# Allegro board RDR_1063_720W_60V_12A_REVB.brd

Outline 161.5 x 81.5 mm; copper layers: TOP, DIELECTRIC 1, BOTTOM. Coordinates in mm from the lower left corner of the outline.
Outline path: 0,81.5 99.62,81.5 99.62,75.94 91.82,75.94 91.82,75.05 99.62,75.05 99.62,69.63 108.57,69.63 108.57,81.5 143.5,81.5 143.5,69.05 161.5,69.05 161.5,56.17 143.5,56.17 143.5,45.12 161.5,45.12 161.5,0 63.75,0 63.75,15.68 47.67,15.68 47.67,0 15.24,0 15.24,15.24 0,15.24 0,81.5

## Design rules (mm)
constraint set DEFAULT: min track width 0.254

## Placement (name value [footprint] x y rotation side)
BR1  GBU8K-BP  [PIDAXBRIDGEGBU8]  23.46 19.25 270 bottom
C1  680 pF  [PINPYCAPRAD470X210LS380040#2]  12.9 78.79 180 top
C2  680 pF  [PINPYCAPRAD470X210LS380040]  100.96 36.9 0 top
C3  1 uF  [PINPCAPRAD_12P6X9P2_LS10_D40]  32.16 13.58 270 top
C4  330 nF  [PI_NP_710X355LS590D040]  42.9 55.81 180 top
C5  330 nF  [PI_NP_710X355LS590D040]  33.16 30.72 180 top
C6  1000 pF  [PISMC1206]  97.71 28.53 180 bottom
C7  680 pF  [PINPYCAPRAD470X210LS380040#2]  7.24 58.83 0 top
C8  10 uF  [PISMC0805]  61.34 72.42 180 bottom
C9  100 uF  [PIPOLCAPCLYD16MMD040]  73.75 76.07 270 top
C9A  100 uF  [PIPOLCAPCLYD16MMD040]  59.02 65.76 253.8 top
C9B  100 uF  [PIPOLCAPCLYD16MMD040]  53.94 41.19 325 top
C10  330 pF  [PISMC0603]  120.5 13.54 90 bottom
C11  10 nF  [PI_NP_CAP250X200LS170D030]  71.9 16.7 45 top
C12  0.1 uF  [PISMC0603]  90.92 9.76 90 top
C13  1000 pF  [PISMC0603]  78.9 19.38 90 bottom
C14  1 uF  [PISMC0805]  88.23 19.03 180 bottom
C15  470 pF  [PISMC0603]  84.61 21.4 0 bottom
C16  1 uF  [PISMC0805]  89 7.65 0 top
C17  1 uF  [PISMC0805]  93.02 19.37 180 bottom
C18  470 pF  [PISMC0805]  82.72 20.8 90 bottom
C19  1 uF  [PISMC0805]  71.15 61.4 0 bottom
C20  220 nF  [PISMC0805]  71.15 59.5 0 bottom
C21  100 uF  [PIPOLCAPCLYD320LS140030]  90.18 34.63 308.8 top
C22  10 uF  [PISMC1206]  77.07 64.53 270 bottom
C23  10 uF  [PISMC1206]  79.37 64.53 270 bottom
C24  1 uF  [PISMC0805]  69.29 42.33 180 bottom
C25  0.015 uF  [PINPXCAPRAD18X6MM040]  85.2 79.32 270 top
C26  150 uF  [PIPOLCAPCLYD320LS140030]  120.27 26.83 310 top
C27  100 uF  [PIPOLCAPCYLD250LS100030]  68.36 39.36 180 top
C28  2.2 uF  [PISMC0603]  122.33 5.17 0 bottom
C29  1 uF  [PISMC1206]  72.94 41.22 0 bottom
C30  680 pF  [PINPYCAPRAD470X210LS380040#3]  99.03 41.95 0 top
C31  2.2 uF  [PISMC1206]  116.5 17.6 270 bottom
C32  390 uF  [PIPOLCAPCLYD500LS200040]  154.22 38.52 180 top
C33  330 pF  [PISMC0603]  118.75 16.56 90 bottom
C34  1.5 nF  [PISMC1206]  120.25 65.24 90 bottom
C35  390 uF  [PIPOLCAPCLYD500LS200040]  136.12 38.45 0 top
C36  1 uF  [PISMC1206]  136.44 36.08 0 bottom
C37  1 uF  [PISMC1206]  156.17 33.47 180 bottom
C38  10 uF  [PISMC1206]  116.43 63.01 270 bottom
C39  470 nF  [PISMC0603]  115.57 53.73 90 bottom
C40  150 pF  [PISMC0603]  117.33 69.98 90 bottom
C41  4.7 nF  [PISMC0805]  123.44 72.96 180 bottom
C42  470 nF  [PISMC0805]  113.78 55.84 270 bottom
C43  1 uF  [PISMC0603]  117.01 47.9 90 bottom
C44  470 pF  [PISMC0603]  116.77 76.3 180 bottom
C45  100 nF  [PISMC0805]  97.5 62.5 90 bottom
C46  1 uF  [PISMC0603]  118.65 50.82 90 bottom
C49  10 uF  [PISMC0805]  113 70.4 0 bottom
C50  0.015 uF  [PINPXCAPRAD18X6MM040]  91.37 64.27 90 top
C51  2.2 uF  [PISMC0805]  125.89 27.51 270 bottom
C52  0.47 uF  [PISMC0805]  98.42 11.08 90 bottom
C53  2.2 uF  [PISMC0603]  127.38 51.61 90 bottom
C54  2.2 uF  [PISMC0603]  114.82 46.59 180 bottom
C55  2.2 uF  [PISMC0603]  132.02 5.24 90 bottom
C56  1 uF  [PISMC1206]  131.39 27.04 180 bottom
C57  100 pf  [PISMC0805]  127.53 76.14 270 bottom
C58  2.2 nF  [PISMC0603]  114.8 25.52 0 bottom
C59  2.2 uF  [PISMC0603]  122.33 6.79 0 bottom
C60  2.2 uF  [PISMC0603]  134.07 5.24 90 bottom
C61  100 pF  [PISMC0603]  118.12 66.79 180 bottom
C62  22 nF  [PISMC0805]  156.46 61.88 90 bottom
C63  1 uF  [PISMC1206]  122.38 41.34 180 bottom
C64  10 uF  [PISMC1206]  118.98 62.4 270 bottom
C100  330 pF  [PISMC0603]  80.14 42.58 180 bottom
C102  470 pF  [PISMC0805]  121.03 78.61 270 bottom
C103  10 nF  [PISMC0805]  139.9 29.29 90 bottom
C104  10 uF  [PISMC0805]  133.76 29.08 90 bottom
C105  1 uF  [PISMC1206]  144.98 20.21 0 bottom
C106  680 pF  [PINPYCAPRAD470X210LS380040#2]  147.33 10.35 0 top
C107  680 pF  [PINPYCAPRAD470X210LS380040#2]  157.84 15.35 180 top
C108  330 nF  [PI_NP_710X355LS590D040]  37.09 75.77 180 top
C109  3300 pF  [PI_NP11D5P5MMTD040]  17.57 45.25 180 top
C110  3300 pF  [PI_NP11D5P5MMTD040]  7.6 50.9 0 top
C111  100 pf  [PISMC0805]  133.43 39.7 180 bottom
C112  10 nF  [PISMC0603]  123.27 46.38 180 bottom
C113  470 nF  [PISMC0603]  121.84 48.01 0 bottom
C114  470 nF  [PISMC0603]  118.9 55.52 90 bottom
C115  100 pf  [PISMC0805]  129.74 76.2 270 bottom
D1  1N4148W RHG  [PI_SM_SOD-123_12]  66.12 77.55 90 bottom
D2  1N5408G  [PIDV300X200X060DO15D0201AD]  34.15 22.68 180 top
D3  ES1A-13-F  [PISMDO214AC12]  90.3 39.07 0 bottom
D4  BAV16WS-7-F  [PISMSOD323]  55.94 75.48 270 bottom
D5  ES1J-LTP  [PISMDO214AC12]  80.22 70.48 90 bottom
D6  BAS16HT1G  [PISMSOD323]  69.66 36.8 180 bottom
D7  S1M  [PISMDSMA]  135.98 17.32 90 bottom
D9  BAV16WS-7-F  [PISMSOD323]  111.96 58.15 270 bottom
D10  S1M  [PISMDSMA]  133.63 14 180 bottom
D13  ES1A-13-F  [PISMDO214AC12]  153.43 58.07 180 bottom
D14  ES1A-13-F  [PISMDO214AC12]  159.54 67 180 bottom
D15  ES1J-LTP  [PISMDO214AC12]  97.84 23.08 270 bottom
D16  ES1J-LTP  [PISMDO214AC12]  115.75 22.83 0 bottom
D18  BAS16HT1G  [PISMSOD323]  130.63 25.01 0 bottom
D19  BAS16HT1G  [PISMSOD323]  122.34 1.32 0 bottom
D20  BAV16WS-7-F  [PISMSOD323]  110.23 58.16 270 bottom
D21  BAV16WS-7-F  [PISMSOD323]  122.43 39.27 270 bottom
D22  BAV16WS-7-F  [PISMSOD323]  81.07 40.9 90 top
D23  BAV16WS-7-F  [PISMSOD323]  121.25 33.09 270 bottom
D24  BAV16WS-7-F  [PISMSOD323]  107.87 4.98 270 bottom
E  CON2  [PI_CONN_QC_TAB_2PIN_LS200]  2.62 57.02 180 top
F1  6.3 A  [PI_V_AX_BEL_0697H]  10.9 69.64 90 top
FL1  Hole_156mils  [PI_HOLE_156MIL]  144.04 61.02 0 top
FL2  Hole_156mils  [PI_HOLE_156MIL]  150.11 65.4 0 top
GND1  CON2  [PI_CONN_QC_TAB_2PIN_LS200]  158.32 24.8 180 top
J10  CON10  [PI_HDRF_1X10_SULLINS]  119.81 3.42 0 top
JP1  J  [PI_JUMPER500-16AWG-SLD]  136.37 23.9 270 top
JP2  J  [PI_JUMPER200-16AWG-SLD]  143.08 27.33 270 top
JP3  J  [PI_JUMPER200-16AWG-SLD]  150.8 27.33 270 top
L  CON2  [PI_CONN_QC_TAB_2PIN_LS200]  7.36 67.54 0 top
L1  20 mH  [DER984_INPUT_CMC]  42.11 50.6 270 top
L2  390 uH  [PITOROID2P650X1170LS560060]  14.91 30.1 180 top
L3  PQ26/25  [PIBOBBINPQ262512P]  40.27 27.01 0 top
L5  1 mH  [PI_CMC_1MH]  29.73 65.85 180 top
MTG_HOLE1  M 3  [PIMTGHOLEM3]  3.52 49.78 0 top
MTG_HOLE2  M 3  [PIMTGHOLEM3P15MMUNP]  73 6 0 top
MTG_HOLE3  M 3  [PIMTGHOLEM3P15MMUNP]  97.5 6 0 top
MTG_HOLE4  M 3  [PIMTGHOLEM3P15MMUNP]  11 11.5 0 top
MTG_HOLE5  M 3  [PIMTGHOLEM3]  153.51 4.42 0 top
MTG_HOLE6  M 3  [PIMTGHOLEM3]  153.5 74.5 0 top
MTG_HOLE7  M 3  [PIMTGHOLEM3]  153.5 50.5 0 top
N  CON2  [PI_CONN_QC_TAB_2PIN_LS200]  20.92 56.44 180 top
NOREF  -  []  68.99 31.93 0 top
NOREF#2  -  []  15.24 0 90 top
NOREF#3  -  []  51.44 -90.81 0 top
NOREF#4  -  []  0 81.5 0 top
Q1  NX7002BKR  [PISMSOT23123_1]  60.84 78.2 90 bottom
Q2  DZT2222A-13  [PISMSOT2231234]  77.91 32.67 90 bottom
Q3  DZT2222A-13  [PISMSOT2231234]  129.79 32.86 90 bottom
Q5  DZT2222A-13  [PISMSOT2231234]  112.72 32.83 270 bottom
Q6  IPP111N15N3 G  [PITO220ABVF1]  139.4 77.25 270 bottom
Q7  TN2130K1-G  [PISMSOT23123_1]  139.12 65.27 90 bottom
Q8  DZT2222A-13  [PISMSOT2231234]  82.67 35.3 180 bottom
Q9  IPP111N15N3 G  [PITO220ABVF1]  139.3 53.15 270 bottom
Q10  TN2130K1-G  [PISMSOT23123_1]  138.35 61.68 90 bottom
Q11  MMBTA06LT1  [PISMSOT23123_1]  125.19 10.65 270 bottom
Q12  AONS62922  [PISMPQFN5X6B]  119.58 23.77 270 bottom
Q13  MMBT3906  [PISMSOT23123_1]  83.46 42.01 270 bottom
R1  510 k  [PISMR1206]  38.4 37.95 90 bottom
R2  510 k  [PISMR1206]  32.66 41.26 270 bottom
R3  150 k  [PISMR1206]  97.71 30.81 180 bottom
R4  4.7 k  [PISMR0805]  60.19 75.48 180 bottom
R5  10 k  [PISMR0805]  57.85 77.39 90 bottom
R6  3.6 MegOhm  [PISMR1206]  69.67 19.77 90 bottom
R7  6.2 M  [PISMR1206]  69.67 25.35 0 bottom
R8  6.2 M  [PISMR1206]  66.95 24.39 270 bottom
R9  6.2 M  [PISMR1206]  75.36 27.67 180 bottom
R10  3.74 M  [PISMR1206]  75.73 25.4 0 bottom
R11  2.2  [PISMR0805]  81.42 26.44 0 bottom
R12  332 k  [PISMR0603]  80.85 19.38 90 bottom
R13  13 k  [PISMR0603]  87.67 11.04 270 top
R14  6.2 M  [PISMR1206]  72.67 22.84 0 bottom
R15  162 k  [PISMR0805]  84.69 23.33 0 bottom
R16  162 k  [PISMR0805]  78.33 23.27 0 bottom
R17  1.50 M  [PISMR1206]  88.1 57.4 0 bottom
R18  11.0  [PISMR0805]  71.15 63.3 0 bottom
R19  10.0K  [PISMR0603]  69.17 32.14 270 bottom
R20  1.50 M  [PISMR1206]  92.8 53.54 270 bottom
R21  2.2  [PISMR0805]  77.74 69.9 270 bottom
R22  1 Mohms  [PISMR1206]  88.81 45.57 180 bottom
R23  200  [PISMR1206]  65.75 34.47 0 bottom
R24  11.0  [PISMR0805]  71.53 39.11 270 bottom
R25  150 k  [PISMR1206]  97.71 33.08 180 bottom
R26  100  [PISMR1206]  94.42 26.24 270 bottom
R27  1000  [PISMR0603]  118.94 11.85 0 bottom
R28  100 kOhms  [PISMR2512]  131.93 22.72 270 bottom
R29  316 k  [PISMR0603]  74.46 38.6 0 bottom
R30  100 k  [PISMR0603]  118.75 13.54 90 bottom
R31  340 k  [PISMR0603]  140.13 6.66 270 bottom
R32  300  [PISMR0603]  117.28 9.67 90 bottom
R33  10.0K  [PISMR0603]  144.55 2.04 0 bottom
R34  340 k  [PISMR0603]  118.12 65.17 180 bottom
R35  2.00 M  [PISMR1206]  96.49 1.6 0 bottom
R36  22 k  [PISMR0603]  116.67 68.41 0 bottom
R37  0.01 Ohm  [PISMR2512]  149.6 35.89 270 bottom
R38  0.01 Ohm  [PISMR2512]  145.77 35.89 270 bottom
R39  10 k  [PISMR0805]  136.2 70.67 90 bottom
R40  200  [PISMR0603]  132.7 64.25 0 bottom
R41  2.2  [PISMR0603]  134.31 69.2 180 bottom
R42  470  [PISMR0603]  125.25 5.17 0 bottom
R43  11.5 k  [PISMR0603]  120.5 16.56 90 bottom
R44  511 k  [PISMR0603]  135.99 64.56 90 bottom
R45  11.8 k  [PISMR0603]  130.19 5.17 180 bottom
R46  3 k  [PISMR0805]  133.9 66.05 180 bottom
R47  11.8 k  [PISMR0603]  114.82 44.7 180 bottom
R49  200  [PISMR0603]  129.19 62.44 270 bottom
R50  10 k  [PISMR0805]  136.5 51.05 90 bottom
R51  2.2 M  [PISMR1206]  102.36 3.26 90 bottom
R52  2.2  [PISMR0603]  136.5 56.76 90 bottom
R53  3 k  [PISMR0603]  118.63 49.32 270 bottom
R54  511 k  [PISMR0603]  135.26 60.92 90 bottom
R55  100  [PISMR0603]  106.18 3.97 270 bottom
R57  3 k  [PISMR0805]  133.38 61.99 180 bottom
R58  75 k  [PISMR1206]  119.57 70.85 0 bottom
R59  43 K  [PISMR0805]  113.46 51.8 0 bottom
R60  15 k  [PISMR0603]  113.59 57.63 0 bottom
R61  750 k  [PISMR0603]  110.49 70.66 90 bottom
R62  715 k  [PISMR0603]  110.49 73.83 90 bottom
R63  255 k  [PISMR0603]  112.15 76.28 0 bottom
R64A  5 k  [PIVRES9MMSQUARE]  119.38 37.62 0 top
R65  20 k  [PISMR0603]  84.67 39.42 0 bottom
R66  255 k  [PISMR0603]  122.53 65.44 90 bottom
R68  10.0K  [PISMR0603]  127.3 56.51 180 bottom
R69  100 k  [PISMR0805]  125.57 54.48 270 bottom
R70  43 k  [PISMR0603]  124.97 46.58 90 bottom
R71  1000  [PISMR0603]  129.83 9.83 90 bottom
R72  100 k  [PISMR0603]  128.09 11.26 270 bottom
R74  4.7 k  [PISMR1206]  87.28 34.74 308.1 bottom
R75  1.5 k  [PISMR1206]  126.3 19.16 90 bottom
R76  150 k  [PISMR0603]  127.3 54.85 0 bottom
R76A  1 k  [PISMR0603]  127.38 49.54 270 bottom
R77  22.6 k  [PISMR0603]  86.09 37.78 180 bottom
R79  10.0K  [PISMR0603]  128.85 17.47 90 bottom
R80  340 k  [PISMR0603]  145.97 5.61 180 bottom
R81  10.0K  [PISMR0603]  144.55 3.95 0 bottom
R82  4.7  [PISMR0603]  117.74 25.52 0 bottom
R84  10.0K  [PISMR0603]  106.18 6.91 270 bottom
R85  11.8 k  [PISMR0603]  126.66 6.8 180 bottom
R87  11.8 k  [PISMR0603]  128.75 6.79 0 bottom
R88  10.0K  [PISMR0603]  119.06 1.32 0 bottom
R89  10.0K  [PISMR0603]  85.26 26.57 0 bottom
R90  150  [PISMR1206]  156.62 57.7 0 bottom
R91  2.2 k  [PISMR0805]  111.54 52.78 270 bottom
R94  1.5  [PISMR0805]  132.74 36.35 270 bottom
R95  1.5  [PISMR0805]  114.77 28.28 0 bottom
R96  68 k  [PISMR0603]  123.6 33.2 270 top
R97  100  [PISMR0805]  123.24 62.08 180 bottom
R98  68 k  [PISMR0603]  117.1 38.43 90 bottom
R101  100 k  [PISMR0603]  45.81 44.19 270 bottom
R102  100 k  [PISMR0603]  25.53 44.19 270 bottom
R103  10 k  [PISMR0805]  125.62 76.15 270 bottom
R104  2.00 M  [PISMR0603]  119.29 72.76 90 bottom
R105  1000  [PISMR0603]  136.9 6.66 270 bottom
R106  36 k  [PISMR1206]  153.5 26.38 270 bottom
R107  36 k  [PISMR1206]  140.32 26.78 270 bottom
R108  36 k  [PISMR1206]  156.17 31.17 180 bottom
R109  36 k  [PISMR1206]  156.35 35.78 180 bottom
R110  36 k  [PISMR1206]  136.44 33.77 0 bottom
R111  0  [PISMR0805]  118.86 78.62 270 bottom
R118  100 k  [PISMR0603]  35.59 66.51 270 bottom
R119  100 k  [PISMR0603]  23.84 66.44 270 bottom
R125  10  [PISMR0603]  64.69 73.56 0 bottom
R126  0  [PISMR0603]  116.1 17.37 270 top
R127  0  [PISMR0603]  119.48 19.18 180 top
R128  100 k  [PISMR0603]  130.7 43.38 180 bottom
R130  1.02 k  [PISMR0603]  129.29 41.29 270 bottom
R131  0.0  [PISMR0603]  133.01 41.73 180 bottom
R132  2 k  [PISMR0603]  129.29 44.95 90 bottom
R133  1 k  [PISMR0603]  109.62 54.25 270 bottom
R134  2.2 k  [PISMR0603]  109.62 49.91 90 bottom
R135  43 k  [PISMR0603]  123.27 44.75 180 bottom
R137  2 k  [PISMR0603]  124.25 57.64 90 bottom
R138  100 k  [PISMR0603]  120.95 58.7 90 bottom
R139  5.11 k  [PISMR0603]  143.03 29.98 180 bottom
R140  0.0  [PISMR0603]  136.89 27.51 180 bottom
R141  9.09 k  [PISMR0603]  135.5 29.18 0 top
R145  5 k  [PIVRES9MMSQUARE]  129.72 37.61 0 top
R147  4.7 k  [PISMR0603]  117.24 54.53 90 bottom
R150  0.0  [PISMR0603]  127.18 44.35 90 bottom
R151  15 k  [PISMR0603]  122.58 59.05 270 bottom
R152  11.8 k  [PISMR0603]  116.83 45.82 270 bottom
R153  11.8 k  [PISMR0603]  124.99 43.42 270 bottom
R154  24 k  [PISMR0603]  80.14 40.39 0 bottom
R155  470 k  [PISMR0603]  87.5 42.9 180 bottom
R156  47 k  [PISMR0603]  86.08 41.07 0 bottom
R157  0  [PISMR0805]  130.23 79.43 180 bottom
RL1  SPST NO  [PI_RELAY_OJE]  63.82 71.45 180 top
RL2  SPST NO  [PI_RELAY_SONGCHUAN895_4PIN]  131.63 18.91 90 top
RT1  16  [PIRAD800X250LS330052]  43.92 75.63 270 top
RV1  320 Vac  [PIDISC610X212LS295X95040]  17.67 75.41 270 top
SG1  0.25mm gap  [PI_SPARK_GAP_0P25MM]  33.22 65.83 270 bottom
SG2  0.25mm gap  [PI_SPARK_GAP_0P25MM]  26.22 65.71 270 bottom
SG3  0.25mm gap  [PI_SPARK_GAP_0P25MM]  42.45 43.46 270 bottom
SG4  0.25mm gap  [PI_SPARK_GAP_0P25MM]  29.08 43.31 270 bottom
T1  PQ35/35  [PI_BOBBIN_BPQ35_35_12P]  115.13 62.93 0 top
T2  EE16  [PI_BOBBIN_EE16_10P_YW-527-00B]  106.8 25.8 0 top
U1  CAP300DG  [PI_IC_SMD_SO8_CAPZERO]  38.2 46.74 270 bottom
U2  PFS7539L  [PIICLBENDESIPLG]  92.49 13.96 0 bottom
U3  LCS7268Z  [PI_POWEDIP_B18PAUNP]  74.37 51.31 180 bottom
U4  TL431CDBZR  [PISMSOT23123_1]  119.23 45.07 0 bottom
U5  LM358D  [PISMSO8]  122.18 52.8 0 bottom
U6  LSR2000C-H005  [PI_IC_INSOP_24D]  113 68.6 180 bottom
U7  INA180A1IDBVR  [PISMSOT235]  137.92 31.22 270 bottom
U8  TLV76050DBZR  [PISMSOT23132]  124.23 25.93 270 bottom
U9  TCLT1000  [PISM-4DIP-SLM-1]  103.82 46.76 180 bottom
U10  INN3692C-H606  [PI_IC_INSOP_24D]  113.4 17.63 180 bottom
UNK+60V1  CON2  [PI_CONN_QC_TAB_2PIN_LS200]  139.7 13.45 0 top
VR1  MMSZ5250B-7-F  [PI_SM_SOD-123_12]  104.43 4.8 90 bottom
VR2  MMSZ5250B-7-F  [PI_SM_SOD-123_12]  65 31.1 180 bottom
VR5  MMSZ5267BT1G  [PI_SM_SOD-123_12]  128.86 22.78 270 bottom
VR7  MMSZ5243BT1G  [PI_SM_SOD-123_12]  113.94 40.1 180 bottom
VR8  MMSZ5241B-7-F  [PI_SM_SOD-123_12]  126.72 29.95 270 top
VR10  MMSZ5242C-E3-08  [PI_SM_SOD-123_12]  88.95 29.11 0 bottom
VR11  MMSZ5267BT1G  [PI_SM_SOD-123_12]  158.35 62.11 90 bottom

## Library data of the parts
BR1 = DISCRETE BRIDGE_+~~-: alternate symbols: (pidaxbridgegbu8_horz)
C1 C2 C4 C5 C7 C11 C29-C31 C34 C36 C37 C56 C63 C105-C110 = CAP NP
C3 = CAP NP: alternate symbols: (pinpcaprad_12p6x9p2_ls10_d400H)
C6 C22 C23 C38 C64 = CAP NP: alternate symbols: (pismc1206_1)
C8 C49 = CAP NP: alternate symbols: (Unisem_RMCF0805UL,CC0805,pismc0805_1)
C9 C9A C9B = CAP POL: alternate symbols: (pipolcapclyd16x37mmD040H)
C10 C33 C40 C43 C46 = CAP NP: alternate symbols: (Unisem_RMCF0603UL,pismc0603_1)
C12 C13 C15 C28 C39 C44 C53-C55 C58-C61 C100 C112-C114 = CAP NP: alternate symbols: (Unisem_RMCF0603UL)
C14 C16-C20 C24 C41 C42 C45 C51 C52 C57 C62 C102-C104 C111 C115 = CAP NP: alternate symbols: (Unisem_RMCF0805UL)
C21 C26 = CAP POL: alternate symbols: (pipolcapclyd320ls140030430h)
C25 C50 = CAP NP: alternate symbols: (pinpxcaprad18x6x12p1mm040H)
C27 = CAP POL: alternate symbols: (pipolcapcyld250ls100030h)
C32 C35 = CAP POL
D1 = DIODE: alternate symbols: (pi_sm_sod-123_12_1)
D2 = DIODE: alternate symbols: (pidv300x472x060do14wbead,pidax800x225060do15do201ad,pidv300x200x060do14wbead)
D3 D5 D7 D10 D13-D16 = DIODE
D4 D6 D9 D18-D24 = DIODE: alternate symbols: (SOD323_UL_IPC,pismsod323_1)
E = CON1_2P_TAB_1
F1 = FUSE: alternate symbols: (PI_V_AX_BEL_0697H_H)
FL1 FL2 = FlyingLead
GND1 UNK+60V1 = CON1_2P_TAB
J10 = HEADER10x1F
JP1-JP3 = JUMPER_1
L = CON1_2P_TAB_0
L1 L5 = TORRID 4P_14_23
L2 = INDUCTOR
L3 = BPQ26/25_12P/GENERIC
MTG_HOLE1-MTG_HOLE7 = MTG_HOLE_M3
N = CON1_2P_TAB_2
Q1 Q7 Q10 = FET_N_GSD
Q2 Q3 Q5 Q8 = NPN_BCEC
Q6 Q9 = FET_N_GDS: alternate symbols: (PI_TO220AB,PITO220ABVF1R,pidvto2203vf1h)
Q11 = NPN_BEC
Q12 = FET_N_SGD_123_4_5678
Q13 = PNP_BEC
R1-R3 R6-R10 R14 R17 R20 R22 R23 R25 R26 R28 R35 R37 R38 R51 R58 R74 R75 R106-R110 = R
R4 R5 R11 R15 R16 R18 R21 R24 R39 R46 R50 R57 R59 R69 R91 R94 R95 R97 R103 R111 R157 = R: alternate symbols: (Unisem_RMCF0805UL)
R12 R13 R19 R27 R29-R34 R36 R40-R45 R47 R49 R52-R55 R60-R63 R65 R66 R68 R70-R72 R76 R76A R77 R79-R82 R84 R85 R87-R89 R96 R98 R101 R102 R104 R105 R118 R119 R125-R128 R130 R131 R133-R135 R138-R141 R147 R150-R156 = R: alternate symbols: (Unisem_RMCF0603UL)
R64A R145 = POT
R90 = R: alternate symbols: (pismr1206_1)
R132 R137 = R: alternate symbols: (Unisem_RMCF0603UL,pismr0603_1)
RL1 = RELAY SPST_NO_OMRON-G6RL
RL2 = RELAY SPST_NO_895-1A
RT1 = THERMISTOR
RV1 = VARISTOR
SG1-SG4 = SPARK_GAP
T1 = BPQ35/35_12P/GENERIC
T2 = BEI16_10P/GENERIC
U1 = CAPZero
U2 = HIPERPFS-3-eSIP-16C: alternate symbols: (piiclbendesiplg_socket)
U3 = HiperLCS2-HB: alternate symbols: (pi_PoweDIP_B18pNH)
U4 = TL431CDBZR
U5 = LM358
U6 = HiperLCS2-SR
U7 = INA180A1IDBVR
U8 = TLV76050DBZR
U9 = OPTO_DIP
U10 = Inno3EP_P15
VR1 VR2 VR5 VR7 VR8 VR10 VR11 = DIODE_ZENER

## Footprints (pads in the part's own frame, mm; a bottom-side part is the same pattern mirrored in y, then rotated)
DER984_INPUT_CMC
  round 3.048 hole 1.524: 1(1.854,0.635) 2(1.676,-13.36) 3(13.183,-13.36) 4(13.386,0.635)
PI_BOBBIN_BPQ35_35_12P
  rect 3.048x3.048 hole 1.778: 1(-17.75,15)
  round 3.048 hole 1.778: 2(-17.75,9.92) 3(-44.598,-83.679) 4(-48.001,-83.654) 5(-17.75,-10.4) 6(-40.229,-82.714) 7(17.81,-15.48) 8(17.81,-10.4) 9(17.81,-5.32) 10(-36.444,-83.654) 11(17.81,9.92) 12(17.81,15)
PI_BOBBIN_EE16_10P_YW-527-00B
  rect 2.032x2.032 hole 1.168: 1(-5.25,6.5)
  round 2.032 hole 1.168: 2(-5.25,3.25) 3(-5.25,0) 4(-23.817,-46.811) 5(-5.25,-6.5) 6(-21.471,-44.041) 7(5.25,-3.25) 8(-24.011,-44.171) 9(5.25,3.25) 10(-21.014,-46.459)
PI_CMC_1MH
  round 2.54 hole 1.27: 1(-3.5,-4.5) 2(3.5,-4.5) 3(3.5,4.5) 4(-3.5,4.5)
PI_CONN_QC_TAB_2PIN_LS200
  rect 3.048x3.048 hole 1.524: 1(0,-2.489)
  round 3.048 hole 1.524: 2(0,2.512)
PI_HDRF_1X10_SULLINS
  rect 1.6x1.6 hole 0.9: 1(0,0)
  round 1.6 hole 0.9: 2(2.54,0) 3(5.08,0) 4(7.62,0) 5(10.16,0) 6(12.7,0) 7(15.24,0) 8(17.78,0) 9(20.32,0) 10(22.86,0)
PI_HOLE_156MIL
  round 6.35 hole 3.962: 1(0,0)
PI_IC_INSOP_24D
  rect 1.75x0.45 smd: 1(0,0) 2(0,-0.75) 3(0,-1.5) 4(0,-2.25) 5(0,-3) 6(0,-3.75) 7(0,-4.5) 8(0,-5.25) 9(0,-6) 10(0,-6.75) 11(0,-7.5) 12(0,-8.25) 13(12.89,-8.25) 14(12.89,-7.5) 15(12.89,-6.75) 24(12.89,0)
  custom 0.438x0.438 smd: 16(12.89,-4.67)
PI_IC_SMD_SO8_CAPZERO
  rect 0.599x2.2 smd: 1(0,0) 2(1.27,0) 3(2.54,0) 4(3.81,0) 5(3.81,5.199) 6(2.54,5.199) 7(1.27,5.199) 8(0,5.199)
PI_JUMPER200-16AWG-SLD
  round 3.048 hole 1.778: 1(0,0) 2(5.08,0)
PI_JUMPER500-16AWG-SLD
  round 3.048 hole 1.778: 1(0,0) 2(12.7,0)
PI_NP11D5P5MMTD040
  round 2.032 hole 1.016: 1(0,0) 2(10,0)
PI_NP_710X355LS590D040
  round 2.032 hole 1.016: 1(0,0) 2(15,0)
PI_NP_CAP250X200LS170D030
  round 1.524 hole 0.762: 1(-2.159,0) 2(2.159,0)
PI_POWEDIP_B18PAUNP
  round 3.15 hole 3.15 unplated: (-13.07,0.08) (11.93,0.08)
  rect 1.473x1.473 hole 0.864: 1(-8.55,-5.97)
  round 1.473 hole 0.864: 2(-6.65,-5.97) 3(-4.75,-5.97) 4(-2.85,-5.97) 5(-0.95,-5.97) 6(0.95,-5.97) 7(2.85,-5.97) 8(4.75,-5.97) 9(6.65,-5.97) 10(8.55,-5.97) 11(8.55,5.97) 13(4.75,5.97) 14(2.85,5.97) 15(0.95,5.97) 16(-0.95,5.97) 17(-2.85,5.97) 18(-4.75,5.97) 20(-8.55,5.97)
PI_RELAY_OJE
  rect 2.032x2.032 hole 1.524: 1(0,0)
  round 2.032 hole 1.575: 2(0,-7.6) 3(15.24,0) 4(12.7,-7.6)
PI_RELAY_SONGCHUAN895_4PIN
  rect 1.321x1.321 hole 0.787: 1(-5.1,-5)
  round 1.397 hole 0.864: 2(-39.35,43.514) 3(-5.1,5) 4(-7.6,0)
PI_SM_SOD-123_12
  rect 1.143x1.397 smd: 1(-1.498,0) 2(2.007,0)
PI_SPARK_GAP_0P25MM
  custom 0.5x0.5 smd: 1(-1.125,0) 2(1.125,0)
PI_V_AX_BEL_0697H
  round 1.524 hole 0.762: 1(0,0) 2(5.08,0)
PIBOBBINPQ262512P
  rect 2.032x2.032 hole 1.27: 1(32.918,-43.51)
  round 2.032 hole 1.27: 2(0,-3.81) 3(40.462,-43.155) 4(0,-15.24) 5(24.054,-43.028) 6(27.737,-43.002) 7(26.111,-44.958) 8(25.4,-19.05) 9(38.075,-43.332) 10(35.585,-43.358) 11(30.175,-43.764) 12(23.622,-45.72)
PIDAXBRIDGEGBU8
  rect 3.048x3.048 hole 1.778: 1(0,0)
  round 3.048 hole 1.778: 2(5.08,0) 3(10.16,0) 4(15.24,0)
PIDISC610X212LS295X95040
  round 2.032 hole 1.016: 1(-2.1,-0.5) 2(8.993,-1.413)
PIDV300X200X060DO15D0201AD
  rect 3.048x3.048 hole 1.524: 1(0,0)
  round 3.048 hole 1.524: 2(7.62,0)
PIICLBENDESIPLG
  rect 1.27x1.27 hole 0.787: 1(0,0)
  round 1.27 hole 0.787: 3(-1.93,-2.388) 4(-2.896,0) 5(-3.861,-2.388) 6(-4.826,0) 7(-5.791,-2.388) 8(-6.756,0) 9(-7.722,-2.388) 10(-8.687,0) 11(-9.652,-2.388) 13(-11.582,0) 14(-12.548,-2.388) 16(-14.478,0)
PIMTGHOLEM3
  round 6.35 hole 3.912: 1(0,0)
PIMTGHOLEM3P15MMUNP
  round 3.15 hole 3.15 unplated: (0,0)
PINPCAPRAD_12P6X9P2_LS10_D40
  round 2.032 hole 1.016: 1(0,0) 2(10,0)
PINPXCAPRAD18X6MM040
  round 2.032 hole 1.016: 1(0,0) 2(15,0)
PINPYCAPRAD470X210LS380040
  round 3.2 hole 1.6: 1(-1.674,1.373) 2(10.363,0.381)
PINPYCAPRAD470X210LS380040#2
  round 3.2 hole 1.6: 1(0,0) 2(9.652,0)
PINPYCAPRAD470X210LS380040#3
  round 3.2 hole 1.6: 1(-2.076,1.321) 2(10.585,0.737)
PIPOLCAPCLYD16MMD040
  rect 2.032x2.032 hole 1.016: 1(0,0)
  round 2.032 hole 1.016: 2(7.62,0)
PIPOLCAPCLYD320LS140030
  rect 1.524x1.524 hole 0.762: 1(-1.778,0)
  round 1.524 hole 0.762: 2(1.778,0)
PIPOLCAPCLYD500LS200040
  rect 2.032x2.032 hole 1.016: 1(0,0)
  round 2.032 hole 1.016: 2(5,0)
PIPOLCAPCYLD250LS100030
  rect 1.524x1.524 hole 0.762: 1(-1.27,0)
  round 1.524 hole 0.762: 2(1.27,0)
PIRAD800X250LS330052
  round 2.54 hole 1.321: 1(0,0) 2(8.382,0)
PISM-4DIP-SLM-1
  rect 1.6x1 smd: 1(-4.85,1.27) 2(-4.85,-1.27) 3(4.85,-1.27) 4(4.85,1.27)
PISMC0603
  rect 0.813x0.965 smd: 1(0,0) 2(1.422,0)
PISMC0805
  rect 1.27x1.27 smd: 1(0,0) 2(2.134,0)
PISMC1206
  rect 1.524x1.524 smd: 1(0,0) 2(3.302,0)
PISMDO214AC12
  rect 2.54x2.286 smd: 1(0,0) 2(4.318,0)
PISMDSMA
  rect 2.032x2.032 smd: 1(0,0) 2(4.013,0)
PISMPQFN5X6B
  rect 0.406x1.27 smd: 1(0,0) 2(1.27,0) 3(2.54,0) 4(3.81,0)
  rect 0.406x1.219 smd: 5(3.81,5.588) 6(2.54,5.588) 7(1.27,5.588) 8(0,5.588)
PISMR0603
  rect 0.813x0.965 smd: 1(0,0) 2(1.422,0)
PISMR0805
  rect 1.27x1.27 smd: 1(0,0) 2(2.134,0)
PISMR1206
  rect 1.524x1.524 smd: 1(0,0) 2(3.302,0)
PISMR2512
  rect 1.93x3.048 smd: 1(0,0) 2(5.994,0)
PISMSO8
  rect 0.61x1.448 smd: 1(-1.905,-2.73) 2(-0.635,-2.73) 3(0.635,-2.73) 4(1.905,-2.73) 5(1.905,2.731) 6(0.635,2.731) 7(-0.635,2.731) 8(-1.905,2.731)
PISMSOD323
  rect 0.762x1.27 smd: 1(0,0) 2(2.54,0)
PISMSOT235
  rect 0.686x1.016 smd: 1(0,0) 2(1.016,0) 3(2.032,0) 4(2.032,2.413) 5(0,2.413)
PISMSOT23123_1
  rect 0.864x1.016 smd: 1(-0.93,-1.1) 2(0.95,-1.1)
  rect 0.864x1.27 smd: 3(0.01,1.186)
PISMSOT23132
  rect 0.864x1.016 smd: 1(-1.88,0) 2(0,0)
  rect 0.864x1.27 smd: 3(-0.94,2.286)
PISMSOT2231234
  rect 1.219x2.235 smd: 1(-2.286,-6.198) 2(0,-6.198) 3(2.286,-6.198)
  rect 3.607x2.235 smd: 4(0,0)
PITO220ABVF1
  round 1.524 hole 1.016: 1(-0.025,0) 2(2.515,0) 3(5.055,0)
PITOROID2P650X1170LS560060
  round 3.048 hole 1.524: 1(0.914,0.051) 2(13.106,-0.025)
PIVRES9MMSQUARE
  round 2.032 hole 1.041: 1(-5.08,0)
  rect 1.524x1.524 hole 0.762: 2(-2.54,5.08) 3(0,0)

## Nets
5VL: C29.1 C45.1 D22.1(K) Q13.2(EMITTER) R65.2 R156.1 U3.7 U6.15
5VS: C49.1 U6.1
+2.5V: C43.1 R53.2 R152.1 R153.1 U4.1 U4.2(VREF)
+5V: C51.1 C104.2 U7.5 U8.1
+12V: C26.1 C46.1 D10.1(K) J10.2 R27.1 R30.1 R53.1 R75.1 R95.2 RL2.1 T2.9 U5.8 U8.2 U10.6
+12V_PMY: C8.1 C17.1 Q8.3 R125.1 RL1.1 U2.1(VCC)
GND_EARTH: C1.2 C7.1 C109.2 C110.1 E.1 E.2 MTG_HOLE1.1
AUX_PRI: C21.1 D3.1(K) D24.2 Q2.2 Q2.4 R11.1 R19.1 R74.1
BAT+: JP1.2 R28.2 R31.1 RL2.4 UNK+60V1.1 UNK+60V1.2
BAT-: C105.2 GND1.1 GND1.2 JP3.2 R106.2
BAT-ADC: J10.9 R31.2 R33.1
BM: D4.1(K) R4.2
BP_RELAY: Q2.3 R23.2
BPP: C27.1 D5.2 D6.1(K) R24.2
BPS: C38.1 C63.1 D21.1(K) D23.1(K) R40.1 R49.1 R97.1 U6.7
CS+: C107.2 JP3.1 R37.2 R38.2 R106.1 R139.1
D5: D14.2 FL2.1 Q6.2 Q7.3
FB: C61.2 D9.1(K) D20.1(K) R34.2 R36.1 U6.5
FL: U3.6 U6.14
GD: C24.2 C27.2 U3.10
GP: C29.2 C45.2 C100.2 R29.2 U3.4 U6.16 U9.3(E)
GSA: C2.2 C26.2 C28.1 C30.2 C31.1 C32.2 C33.2 C35.2 C36.2 C37.2 C38.2 C43.2 C46.2 C51.2 C53.2 C54.2 C55.1 C56.2 C59.1 C60.1 C63.2 C64.2 C103.2 C104.1 C111.2 C114.2 D16.2 J10.1 J10.7 Q6.3(S) Q9.3(S) Q11.2(EMITTER) Q12.1 Q12.2 Q12.3(S3) R33.2 R37.1 R38.1 R39.1 R43.2 R50.1 R64A.3 R69.1 R72.2 R75.2 R76.1 R81.2 R82.2 R108.2 R109.2 R110.2 R126.1 R130.2 R134.1 R138.1 R140.1 R145.3 U4.3 U5.4 U6.12 U7.2 U8.3 U9.2 U10.1 U10.2 VR7.2 VR8.2
GSB: C34.2 C40.2 C41.2 C49.2 C57.2 C61.1 C115.2 R36.2 R66.2 R103.2 R104.2 T1.11 U6.2
IOUT: R105.1 R137.2 R141.2 U7.1
IOUT-ADC: J10.8 R105.2
IS: C44.1 C57.1 C102.2 R103.1 R111.2
MCU_IPWM: C59.2 R47.2 R85.1
MCU_RELAY: J10.6 R71.1
MCU_VPWM: C60.2 R68.2 R87.1
NC8: U10.8
NC9: U10.9
NC10: U10.10
NC11: U10.11
NC12: U10.12
ON: D19.2 J10.3
OUT+: C32.1 C34.1 C35.1 C36.1 C37.1 C62.2 C106.1 C111.1 D18.2 JP2.1 R34.1 R80.1 R94.1 R98.2 R107.1 R108.1 R109.1 R110.1 R131.1 T1.7 T1.8 T1.9 VR11.2
OUT++: C105.1 D7.2 JP1.1 JP2.2 R107.2 RL2.2
PG_PFS: R77.1 U2.8
REFCC: C54.1 R47.1 R64A.2(WIPER) R138.2 R151.1 R152.2
RTN: BR1.4 C3.2 C8.2 C9.2 C9A.2 C9B.2 C11.2 C21.2 C25.2 C30.1 C52.2 L3.4 Q1.2(S) R5.2 R74.2 T1.5 T2.2 U2.10 U3.11(S) U10.16 VR2.2 VR10.2
SOURCE: U2.11
VBULK: C2.1 C6.1 C9.1 C9A.1 C9B.1 C11.1 C50.1 D2.1(K) R3.1 R6.1 R17.1 R25.1 R35.1 T2.3 U2.16 U3.20
VOUT-ADC: J10.10 R80.2 R81.1
VRECT: BR1.1 C3.1 D2.2 L3.2 R8.2
N13075197: F1.1 L.1 L.2
N13075201: C1.1 F1.2 RL1.4(NO) RT1.1 RV1.1
N13075229: C108.1 L5.1 R118.1 RL1.3 RT1.2 SG1.1
N13075257: C4.1 C109.1 L1.1 L5.4 R101.1 R118.2 SG1.2 SG3.1
N13075293: BR1.2 C5.1 L1.4 R1.1 R101.2 SG3.2
N13075321: BR1.3(AC2) L2.2
N13075467: R1.2 U1.1 U1.2 U1.3 U1.4
N13075621: C7.2 C108.2 L5.2 N.1 N.2 R119.1 RV1.2 SG2.1
N13075629: C4.2 C110.2 L1.2 L5.3 R102.1 R119.2 SG2.2 SG4.1
N13075705: C5.2 L1.3 L2.1 R2.2 R102.2 SG4.2
N13075741: R2.1 U1.5 U1.6 U1.7 U1.8(NC8)
N13076159: D1.2 Q1.3 RL1.2
N13076167: D1.1(K) R125.2
N13076321: Q1.1 R4.1 R5.1
N13076547: R8.1 R9.2
N13076615: L3.8 U2.13
N13076627: R6.2 R7.1
N13076649: C18.1 R14.2 R16.1 U2.7
N13076657: C13.1 R12.1 U2.9
N13076673: R9.1 R10.1
N13076695: C12.1 R13.1 U2.6
N13076727: C15.1 R10.2 R15.1 U2.5
N13076745: R7.2 R14.1
N13076899: C12.2 C13.2 C14.2 C15.2 C16.2 C17.2 C18.2 R12.2 R15.2 R16.2 U2.4
N13076903: C14.1 U2.3
N13077057: C16.1 R13.2
N13077081: Q8.2 Q8.4 R11.2 R89.1
N13077159: Q8.1 R89.2 VR10.1
N13081652: C19.1 R18.1 U3.13
N13081672: R17.2 R20.1
N13081712: C19.2 C20.2 C22.2 C23.2 T1.2 U3.15
N13081716: C22.1 C23.1 R18.2 R21.2
N13081774: C20.1 U3.14
N13081802: C25.1 C50.2 T1.1
N13081806: R20.2 R22.1
N13081894: D5.1(K) R21.1
N13081936: C100.1 D22.2 R22.2 R65.1 R77.2 R154.1 U3.2
N13081966: C102.1 C115.1 R111.1 R157.2
N13082106: R157.1 T1.12
N13082142: D4.2 U3.9
N13082252: R29.1 U3.5
N13082394: C24.1 R24.1 U3.8
N13082422: D6.2 R23.1
N13082998: R79.1 R88.1 U9.1
N13083006: D19.1(K) R88.2
N13083046: R155.1 R156.2 U9.4
N13083116: R79.2 VR5.2
N13083120: C56.1 D18.1(K) VR5.1
N13129300: D13.2 FL1.1 Q9.2 Q10.3
N13129338: C106.2 C107.1 MTG_HOLE5.1
N13129680: R90.2 VR11.1
N13130082: Q6.1 R39.2 R41.1
N13130158: Q7.1 R40.2 R44.1
N13130170: Q7.2(S) R44.2 R46.1
N13130230: R41.2 U6.8
N13130322: R46.2 U6.10
N13130482: Q9.1 R50.2 R52.1
N13130510: C40.1 R58.1 R104.1 U6.4
N13130530: Q10.1 R49.2 R54.1
N13130550: Q10.2(S) R54.2 R57.1
N13130620: R52.2 U6.9
N13130700: C41.1 R58.2
N13130736: R57.2 U6.11
N13130824: R61.1 U6.3
N13130832: R61.2 R62.1
N13130836: R62.2 R63.1
N13130840: C44.2 R63.2
N13131010: R66.1 U6.6(PS)
N13134664: C28.2 R42.1 R85.2
N13134676: J10.4 R42.2
N13134874: C55.2 R45.1 R87.2
N13134886: J10.5 R45.2
N13135254: R35.2 R51.1
N13135258: C6.2 R3.2 R25.2 R26.1
N13135288: C58.1 D16.1(K) Q12.5 Q12.6 Q12.7 Q12.8 R32.1 T2.7
N13135376: D15.1(K) R26.2
N13135380: D15.2 T2.5 U10.24
N13135402: Q12.4 R127.1
N13135462: R126.2 R127.2 U10.5
N13135530: D3.2 T2.1
N13135582: Q2.1 R19.2 VR2.1
N13135930: C58.2 R82.1
N13136072: C10.1 R27.2
N13136170: C10.2 C33.1 R30.2 R43.1 U10.3
N13136174: D24.1(K) R55.1 R84.2
N13136212: R32.2 U10.7
N13136306: C31.2 U10.4
N13136428: R55.2 VR1.1
N13136440: C52.1 R84.1 U10.14 VR1.2
N13140087: R51.2 U10.13(VPIN)
N13191912: C39.1 R59.2 R151.2 U5.2
N13191920: C39.2 C42.1 R147.1 U5.1
N13192176: C42.2 R59.1
N13192240: C103.1 R139.2 U7.3
N13192354: D9.2 R60.1
N13192496: R137.1 U5.3
N13192500: R140.2 R141.1 U7.4
N13192960: R128.1 R131.2
N13193004: R128.2 R130.1 R132.1
N13193032: R76A.1 R132.2 U5.5
N13193186: C53.1 R68.1 R76.2 R76A.2
N13193272: C112.2 C113.1 R91.2 R135.2 U5.7(OUT)
N13193284: R91.1 R133.2 R134.2
N13193324: C113.2 R69.2 R70.2 R150.2 U5.6
N13193524: C112.1 R70.1 R135.1
N13193682: R145.2(WIPER) R150.1 R153.2
N13193934: Q3.2 Q3.4 R94.2 R96.1
N13193966: D21.2 Q3.3
N13193994: D23.2 Q5.3
N13194018: Q5.2 Q5.4 R95.1
N13194026: Q3.1 R96.2 VR8.1
N13194030: Q5.1 R98.1 VR7.1
N13194134: C64.1 R97.2
N13204238: D20.2 R133.1
N13219296: C114.1 R60.2 R147.2
N13249684: D7.1(K) R28.1
N13249824: D10.2 Q11.3 RL2.3
N13249932: Q11.1 R71.2 R72.1
N13259403: C62.1 D13.1(K) D14.1(K) R90.1
N13332978: Q13.1 R155.2
N13335649: Q13.3 R154.2

Pads without a net: L3 1 3 5 6 7 9 10 11 12; MTG_HOLE6 1; MTG_HOLE7 1; R64A 1; R145 1; T1 3 4 6 10; T2 4 6 8 10; U2 14; U3 1 3 16 17 18; U6 13 24; U10 15

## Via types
v1: diameter 1.27, hole 0.711, TOP to BOTTOM, 118 vias
v2: diameter 0.457, hole 0.305, TOP to BOTTOM, 15 vias
v3: diameter 0.6, hole 0.3, TOP to BOTTOM, 164 vias
v4: diameter 0.762, hole 0.381, TOP to BOTTOM, 16 vias
v5: diameter 0.813, hole 0.508, TOP to BOTTOM, 3 vias
v6: diameter 0.508, hole 0.305, TOP to BOTTOM, 1 via
v7: diameter 0.55, hole 0.35, TOP to BOTTOM, 1 via
v8: diameter 0.762, hole 0.305, TOP to BOTTOM, 1 via
v9: diameter 1, hole 0.4, TOP to BOTTOM, 7 vias

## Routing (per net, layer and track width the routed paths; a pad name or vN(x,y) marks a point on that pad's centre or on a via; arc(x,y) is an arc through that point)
5VL: length 71.7
  TOP w0.254: D22.1 v2(84.2,40.9)
  TOP w0.305: U3.7 71.55,45.31 71.55,40.84 v4(72.97,39.42) 74.52,37.87 74.55,37.87 74.59,37.84 v4(87.45,37.84) 87.69,38.07 87.73,38.07 94.48,44.82 94.48,57.28 v3(96.12,58.93)
  BOTTOM w0.254: 71.55,44.95 71.55,44.95
  BOTTOM w0.305: U6.15 98.15,61.85 C45.1 97.45,62.45 96.5,62.45 95.9,61.86 95.9,60.54 96.12,60.32 v3(96.12,58.93) ; 72.28,43.21 71.52,43.97 U3.7
  BOTTOM w0.508: v4(87.45,37.84) 87.45,38.99 87.02,39.42 R65.2 86.08,39.43 R156.1 86.07,41.06 Q13.2
  BOTTOM w1: v4(72.97,39.42) 72.94,39.45 C29.1 72.94,42.55 72.28,43.21 71.55,43.94 71.55,44.95
5VS: length 1.8
  BOTTOM w0.305: C49.1 113,69.36 113,69.36 U6.1
+2.5V: length 15.1
  BOTTOM w0.508: R53.2 118.31,47.57 U4.1 118.11,45.97 116.98,45.97 R152.1 ; R53.2 119.74,47.9 120.18,47.45 U4.2 120.65,45.7 120.65,43.93 121.16,43.42 R153.1 ; R53.2 C43.1
+5V: length 13.9
  BOTTOM w0.508: U8.1 125.59,27.81 C51.1 125.89,28.41 126.21,28.73 131.32,28.73 131.57,28.98 131.57,29.74 132.61,30.78 133.32,30.78 C104.2 U7.5
+12V: length 147.2
  TOP w0.381: J10.2 124.99,6.07 128.65,6.07 129.82,7.24 129.82,12.24 131.58,14 v3(133.63,14) ; v3(125.24,16.71) 126.62,16.71 130.1,20.19 130.1,31.83 126.97,34.95 126.97,37.64 124.66,39.95 122.66,39.95 121.08,41.53 121.08,48.38 v3(118.65,50.82)
  TOP w1: T2.9 117.94,29.05 118.8,28.19 C26.1 119.13,22.99 122.07,20.04 v1(122.07,18.67) 122.07,9.88 117.73,5.54 117.73,2.4 118.73,1.4 121.09,1.4 122.35,2.65 J10.2
  BOTTOM w0.305: R27.1 118.75,12.05 R30.1 ; R27.1 118.94,10.96 119.21,10.69 121.97,10.69 122.3,11.02 122.3,17.48 122.07,17.7 v1(122.07,18.67) ; R27.1 118.13,11.85 117.28,12.7 115.88,12.7 114.71,13.88 U10.6 ; 118.88,28.15 119.07,27.97
  BOTTOM w0.381: R53.1 118.63,50.24 118.65,50.25 v3(118.65,50.82) 119.89,50.82 120.27,50.44 120.27,50.08 U5.8
  BOTTOM w0.508: v3(125.24,16.71) 124.33,16.71 123.46,17.59 123.46,19.16 ; U8.2 123.48,25.93 123.19,26.21 123.19,28.29 122.86,28.63 119.96,28.63 119.53,28.19 C26.1
  BOTTOM w0.7: v3(133.63,14) 133.82,13.81 RL2.1
  BOTTOM w1.27: R75.1 122.56,19.16 v1(122.07,18.67)
+12V_PMY: length 98.6
  TOP w0.508: v4(64.8,28.47) v4(78.79,28.47) 84.79,22.48 v4(89.31,22.48)
  BOTTOM w0.508: v4(89.31,22.48) 89.31,21.67 90.27,20.7 92.07,20.7 93.02,19.76 C17.1 93.02,14.49 U2.1 ; RL1.1 63.82,61.97 57.75,55.9 57.75,54.3 55.49,52.04 55.49,49.38 57.75,47.12 57.75,47.09 60.47,44.37 64.19,44.37 64.69,43.86 64.69,39.8 63.98,39.09 63.98,33.13 64.8,32.32 v4(64.8,28.47) ; Q8.3 79.42,29.1 v4(78.79,28.47)
  BOTTOM w0.8: RL1.1 64.69,72.33 R125.1
  BOTTOM w1: RL1.1 62.82,72.45 61.38,72.45 C8.1
AUX_PRI: length 92.2
  TOP w0.381: v6(107.49,2.46) 107.49,1.09 106.76,0.36 101.07,0.36 100.38,1.04 100.38,7.47 98.58,9.27 96.09,9.27 94.72,10.64 v4(94.72,18.21)
  TOP w1: v1(75.81,35.33) 77.11,35.33 v1(77.13,35.3) 78.41,35.3 v1(78.43,35.33) 88.38,35.33 C21.1
  BOTTOM w0.305: 77.55,32.93 77.55,32.2 71.75,32.2 71.75,32.64 Q2.2 71.22,32.17 70.09,32.17 70.06,32.14 R19.1
  BOTTOM w0.508: R11.1 80.71,27.15 77.67,27.15 77.09,27.74 77.09,31.12 77.79,31.82 77.79,32.54 Q2.4 ; v4(94.72,18.21) 94.72,19.86 92.58,22 92.58,36.91 90.43,39.07 D3.1
  BOTTOM w1: D3.1 90.3,37.01 C21.1 88.55,36.01 R74.1
BAT+: length 10
  BOTTOM w0.508: R28.2 131.63,16.43 RL2.4 ; UNK+60V1.1 140.13,10.53 R31.1
  vias: v1(133.17,11.99) v1(133.17,10.72) v1(134.44,11.99) v1(134.44,10.72) v1(136.02,9.14) v1(137.29,9.14) v1(139.22,13.59) v1(140.49,13.59) v1(141.99,16.76) v1(141.99,15.49) v1(141.99,14.22) v1(141.99,12.95) v1(141.99,11.68) v1(141.99,10.41) v1(141.99,9.14) v1(143.26,15.49) v1(143.26,14.22) v1(143.26,12.95) v1(143.26,11.68) v1(143.26,10.41) v1(143.26,9.14)
BAT-:
  vias: v1(149.97,20.32) v1(149.97,19.05) v1(151.24,20.32) v1(151.24,19.05) v1(152.51,21.59) v1(152.51,20.32) v1(152.51,19.05) v1(153.78,21.59) v1(153.78,20.32) v1(153.78,19.05) v1(155.05,22.86) v1(155.05,21.59) v1(155.05,20.32) v1(155.05,19.05) v1(156.32,24.13) v1(156.32,20.32) v1(156.32,19.05) v1(157.59,24.77) v1(157.59,19.05) v1(158.86,24.77)
BAT-ADC: length 6.8
  BOTTOM w0.381: R33.1 141.51,2.04 J10.9
  BOTTOM w0.508: R31.2 J10.9
BM: length 2.1
  BOTTOM w0.7: R4.2 55.94,75.48 D4.1
BP_RELAY: length 2.9
  BOTTOM w1: R23.2 69.54,34.95 Q2.3
BPP: length 76.8
  TOP w0.508: C27.1 69.63,38.09 69.26,37.72 66.12,37.72 62.82,41.02 v4(62.82,45.67)
  BOTTOM w0.508: C27.1 69.66,39.33 D6.1 69.67,36.8 71.35,36.8 R24.2 ; v4(62.82,45.67) 60.54,45.67 58.89,47.32 56.4,49.81 56.4,51.74 58.61,53.95 58.61,55.62 64.95,61.95 64.95,67.61 67.46,70.13 67.46,78.38 68.83,79.75 77.6,79.75 80.22,77.13 D5.2
BPS: length 60.7
  TOP w0.381: v3(125.07,50.72) 122.81,48.46 v3(122.81,41.81)
  BOTTOM w0.381: v3(125.07,50.72) 129.24,50.72 129.74,51.23 129.74,56.18 124.8,61.13 124.19,61.13 R97.1 ; R97.1 124.47,63.31 128.24,63.31 129.11,62.44 R49.1 129.27,62.44 131.08,64.25 R40.1 ; R97.1 121.69,63.63 117.2,63.63 116.58,63.01 C38.1 116.43,63.22 115.55,64.1 U6.7 ; C63.1 122.38,40.39 122.43,40.33 D21.1 121.54,39.27 121.25,38.97 D23.1
CS+: length 23.4
  TOP w1.27: C107.2 148.19,24.72 JP3.1
  BOTTOM w0.508: R139.1 143.03,32.99 143.59,33.55 147.35,33.55 147.7,33.2 147.7,30.94
  vias: v1(148.89,26.72) v1(148.89,25.45) v1(150.16,25.45) v1(151.43,25.45) v1(153.44,28.17)
D5: length 16.2
  BOTTOM w0.508: Q7.3 140.42,65.28 141.11,65.97 150.43,65.97 ; FL2.1 151.71,67 D14.2
  vias: v3(140.74,75.31) v3(140.74,74.61) v3(141.44,75.31) v3(141.44,74.61) v3(142.14,75.31) v3(142.14,74.61) v3(142.14,73.91) v3(142.14,73.21) v3(142.14,72.51) v3(142.14,71.81) v3(142.14,71.11) v3(142.14,70.41) v3(142.14,69.71) v3(142.14,69.01) v3(142.14,68.31) v3(142.14,67.61) v3(142.84,75.31) v3(142.84,74.61) v3(142.84,73.91) v3(142.84,73.21) v3(142.84,72.51) v3(142.84,71.81) v3(142.84,71.11) v3(142.84,70.41) v3(142.84,69.71) v3(142.84,69.01) v3(142.84,68.31) v3(142.84,67.61) v3(143.54,68.31) v3(143.54,67.61) v3(144.24,68.31) v3(144.24,67.61) v3(144.94,68.31) v3(144.94,67.61) v3(145.64,68.31) v3(145.64,67.61) v3(146.34,68.31) v3(146.34,67.61) v3(147.04,68.31) v3(147.04,67.61)
FB: length 18.7
  BOTTOM w0.305: U6.5 111.45,65.6 110.79,64.95 110.79,59.66 110.23,59.1 D20.1 110.24,58.15 D9.1
  BOTTOM w0.381: U6.5 114.67,65.6 115.87,66.79 C61.2
  BOTTOM w0.508: R34.2 116.7,66.79 C61.2 116.67,66.82 R36.1
FL: length 49.8
  TOP w0.305: U3.6 73.42,40.32 75.1,38.63 87.5,38.63 93.92,45.05 93.92,58.04 95.9,60.02 v3(96.87,60.02)
  BOTTOM w0.305: U6.14 97.16,61.1 96.87,60.81 v3(96.87,60.02)
GD: length 6.6
  BOTTOM w0.305: U3.10 65.85,45.31 65.85,44.95
  BOTTOM w1: C27.2 67.09,42.26 C24.2 65.85,43.63 65.85,44.95
GP: length 115.6
  TOP w0.305: 98.72,60.1 101.09,60.1 101.37,60.38 101.37,62.46 100.94,62.89 ; 98.72,60.1 97.82,60.1 97.54,60.38 97.54,60.76 96.56,61.74 95.87,61.74 ; 98.72,60.1 98.72,59.87 95.12,56.27 95.12,44.32 87.85,37.05 73.72,37.05 70.92,39.86 70.92,42.55 ; 77.25,44.95 77.25,45.31 U3.4
  TOP w1: v3(95.87,64.25) 95.87,61.74 93,58.87 93,46.49 93.01,46.47 v3(93.01,45.49) 87.06,39.54 78.49,39.54 77.25,40.78 77.25,44.95
  BOTTOM w0.305: 77.25,44.95 77.25,45.31 U3.4
  BOTTOM w0.508: U9.3 v3(93.01,45.49)
  BOTTOM w0.762: 77.25,42.6 76.24,41.59 C29.2 75.88,40.87 R29.2 ; 77.25,42.6 77.27,42.58 C100.2 ; 77.25,42.6 77.25,44.95
  vias: v3(95.85,65.19) v3(96.62,65.47) v3(98.68,64.55) v3(98.68,64.53) v3(99.98,65.93) v3(100.43,65.46)
GSA: length 384.4
  TOP w0.381: C35.2 139.02,36.35 134.65,36.35 v3(131.29,39.7)
  TOP w0.508: 136.75,71.35 135.31,71.35 134.37,70.41 134.37,63.47 130.47,59.58 118.16,59.58 v1(116.73,58.15) ; R126.1 114.91,17.37 v2(114.83,17.3) ; v1(126.48,23.98) 126.48,26.62 126.72,26.86 VR8.2
  TOP w0.635: 129.79,59.58 129.79,46.02 131.95,43.87 135.91,43.87 136.03,43.98 136.03,44.98 v1(137.03,45.97) ; v1(144.94,35.58) 134.19,35.58 130.21,39.56 130.21,44.08 128.65,45.64 v1(128.65,53.01)
  TOP w0.8: v1(126.48,23.98) 127.69,23.98 129.16,25.45 129.16,31.55 125.68,35.03 124.59,35.03 119.13,40.49 v1(119.13,41.5) 119.13,43.95 115.32,47.76 v1(115.32,48.97) 115.32,56.74 v1(116.73,58.15) 118.15,58.15 118.41,58.42 127.25,58.42 128.65,57.02 v1(128.65,53.01)
  TOP w1: C30.2 111.28,41.03 111.28,40.87 111.33,40.83 C2.2 117.77,30.84 119.15,30.84 121.41,28.58 C26.2 123.47,23.41 123.47,8.83 119.81,5.17 J10.1
  BOTTOM w0.305: Q11.2 127.17,8.81 132.18,8.81 133.2,7.8 134.37,7.8 134.69,7.47 134.72,7.47 134.96,7.24 134.96,5.37 134.83,5.24 C60.1
  BOTTOM w0.381: R138.1 119.38,58.7 C64.2 ; U5.4 124.09,55.01 124.36,54.74 125.32,54.74 R69.1 ; 113.97,18.37 113.97,17.64 113.96,17.63 U10.1 U10.2 113.4,16.83 115.65,16.83 116.22,17.4 ; C54.2 113.4,47.52 113.85,47.97 115.24,47.97 115.32,48.05 v1(115.32,48.97) 110.64,48.97 109.7,49.91 R134.1 ; R81.2 R33.2 145.97,1.12 145.62,0.76 137.71,0.76 J10.7 ; C38.2 114.96,59.71 114.32,60.35 U6.12 111.91,60.35 111.48,60.78 111.48,64.79 111.66,64.97
  BOTTOM w0.508: C46.2 118.18,52.24 117.47,51.54 117.47,49.78 C43.2 116.13,49.32 115.77,48.97 v1(115.32,48.97) ; C55.1 C60.1 133.76,4.93 133.76,4.21 134.55,3.42 J10.7 ; U4.3 119.25,41.76 119.08,41.59 C63.2 119.08,40.07 119.38,39.76 R64A.3 ; 119.81,6.79 J10.1 ; 119.81,6.79 119.81,7.67 120.32,8.18 123.17,8.18 124.69,9.7 Q11.2 126.42,9.83 R72.2 ; 119.81,6.79 C59.1 122.33,6.78 C28.1 ; 111.94,41.45 111.94,44.2 110.64,45.49 U9.2 ; 111.94,41.45 115.84,41.45 115.87,41.43 117.81,41.43 117.96,41.58 119.05,41.58 v1(119.13,41.5) ; 111.94,41.45 VR7.2 ; v3(131.29,39.7) 131.13,39.87 R130.2 129.29,38.05 R145.3 ; R140.1 136.74,27.66 136.74,30.23 ; C104.1 134.9,30.23 136.74,30.23 ; R76.1 125.94,54.85 R69.1 125.93,54.48 C53.2 128.62,53.04 v1(128.65,53.01) ; 136.74,30.23 137.9,30.23 U7.2 138.63,30.2 139.85,31.42 C103.2 141.5,31.42 142.04,31.95 142.04,33.08 143.27,34.32 147.29,34.32 147.65,34.67 147.65,36.93 ; v1(116.73,58.15) 116.73,58.02 117.81,56.95 C114.2 ; 116.5,17.4 116.22,17.4
  BOTTOM w0.635: 137.03,48.09 136.5,48.62 R50.1 ; 137.03,48.09 139.29,48.09 ; 137.03,48.09 v1(137.03,45.97)
  BOTTOM w0.7: D16.2 121.06,21.85 121.01,21.8 121.01,19.48 120.5,18.97 R43.2
  BOTTOM w0.8: v1(126.48,23.98) 122.9,23.98 C26.2 ; v1(126.48,23.98) 126.69,23.98 127.41,24.69 127.41,26.36 C56.2 ; v1(126.48,23.98) 126.07,24.38 126.07,25.19 C51.2 ; C35.2 139.75,37.07 C36.2 139.74,36.07 R110.2 ; C64.2 118.03,58.15 v1(116.73,58.15) 116.43,58.46 C38.2
  BOTTOM w1: R75.2 126.48,22.64 v1(126.48,23.98)
  vias: v3(136.02,69.37) v3(136.02,68.67) v3(136.72,69.37) v3(136.72,68.67) v3(137.42,69.37) v3(137.42,68.67) v3(138.12,72.17) v3(138.12,71.47) v3(138.12,70.77) v3(138.12,70.07) v3(138.12,69.37) v3(138.12,68.67) v3(138.82,70.77) v3(138.82,70.07) v3(138.82,69.37) v3(138.82,68.67) v3(139.52,70.77) v3(139.52,70.07) v3(139.52,69.37) v3(139.52,68.67) v3(147.85,38.5) v3(148.03,39.19) v3(148.01,37.82) v3(148.49,39.7) v3(148.49,37.34) v3(149.2,39.9) v3(149.2,37.13) v3(149.96,39.7) v3(149.91,37.34) v3(150.42,37.8) v3(150.5,39.17) v3(150.62,38.5)
GSB: length 56.3
  BOTTOM w0.305: C41.2 121.31,69.61 C34.2 ; 114.1,67.85 114.1,67.85
  BOTTOM w0.381: C57.2 127.51,74.01 127.5,74.01 R103.2 124.72,74.01 123.57,75.16 112.93,75.16 111.63,73.86 111.63,68.23 112.01,67.85 U6.2 114.1,67.85 ; 114.63,69.83 114.63,68.38 114.1,67.85 ; 129.22,74.01 130.38,72.85 132.94,72.85 T1.11
  BOTTOM w0.508: C57.2 129.68,74.01 C115.2 ; C61.1 118.12,68.38 R36.2 118.23,68.55 C34.2 121.76,68.55 122.53,67.78 R66.2 ; C41.2 120.08,74.19 R104.2 117.98,74.19 117.33,73.53 C40.2 116.13,71.41 C49.2 115.13,70.33 114.63,69.83
IOUT: length 79.1
  TOP w0.305: v1(138.53,6.71) 142.88,6.71 144.78,8.6 144.78,16.72 143.54,17.96 136.45,17.96 133.96,20.45 133.96,25.34 136.92,28.3 R141.2 136.92,31.4 136.93,31.41 v3(136.93,32.06) 131.73,32.06 128.55,35.24 128.55,43.69 126.5,45.74 v2(126.5,57.53)
  BOTTOM w0.305: R105.1 136.95,6.71 v1(138.53,6.71)
  BOTTOM w0.381: v3(136.93,32.06) 137.78,31.22 U7.1 ; v2(126.5,57.53) 124.96,59.06 R137.2
IOUT-ADC: length 2.1
  BOTTOM w0.508: J10.8 137.59,4.55 R105.2
IS: length 11
  BOTTOM w0.381: C57.1 125.63,76.14 R103.1 125.29,76.48 C102.2 119.95,76.48 119.95,76.48 R111.2 118.68,76.3 C44.1
MCU_IPWM: length 46.1
  TOP w0.381: v4(124.43,8.18) 124.43,27.16 116.2,35.38 116.2,38.13 113.4,40.93 v4(113.4,44.7)
  BOTTOM w0.305: v4(124.43,8.18) 126.18,8.18 126.66,7.69 R85.1
  BOTTOM w0.381: C59.2 123.75,7.5 v4(124.43,8.18)
MCU_RELAY: length 10.1
  TOP w0.508: J10.6 132.51,7.72 v1(133.63,8.84)
  BOTTOM w0.508: v1(133.63,8.84) 132.87,9.59 130.07,9.59 R71.1
MCU_VPWM: length 58.1
  TOP w0.305: v2(125.83,56.26) 125.83,40.77 127.81,38.79 127.81,34.96 130.7,32.07 130.7,19.32 128.83,17.45 v4(128.83,8.03)
  BOTTOM w0.305: R87.1 128.75,7.95 v4(128.83,8.03) 132.18,8.03 133.54,6.66 C60.2
ON: length 2.1
  BOTTOM w0.508: D19.2 124.89,1.33 J10.3
OUT+: length 160.9
  TOP w0.508: 143.1,27.3 144.54,25.86 145.46,25.86 147.05,24.28 147.05,18.25 145.82,17.03 145.82,12.72 145.84,12.7 145.84,11.84 C106.1 ; v3(120.15,65.29) 120.89,65.29 121.77,66.18 121.77,69.29 121.41,69.65 112.29,69.65 111.2,68.55 111.2,49.2 115.37,45.03 115.37,41.62 v4(117.07,39.91) 117.64,39.34 117.64,35.9 123.88,29.67 v4(128.12,29.67) ; 152.37,44.15 152.02,44.5 143.59,44.5 143.08,45.01 143.08,56.41 143.51,56.85 154.28,56.85 157.33,59.89 v2(157.33,64.12)
  BOTTOM w0.254: v4(117.07,39.91) 117.07,39.89 R98.2
  BOTTOM w0.381: R34.1 120.17,65.17 C34.1
  BOTTOM w0.508: v4(128.12,29.67) 130.33,29.67 132.16,31.5 132.16,32.13 132.79,32.77 134.21,32.77 134.7,33.25 134.7,36.96 136.12,38.38 C35.1 135.46,38.45 133.81,40.11 ; R107.1 140.32,27 139.54,26.21 134.12,26.21 133.17,25.27 D18.2 ; C106.1 147.33,7.04 145.97,5.69 R80.1 ; VR11.2 v2(157.33,64.12) 156.56,64.12 C62.2
  vias: v1(131.67,55.74) v1(131.67,54.35) v1(131.67,50.71) v1(131.67,49.31) v1(132.84,45.33) v1(132.94,55.08) v1(132.94,50.05) v1(134.19,55.74) v1(134.19,54.35) v1(134.19,50.71) v1(134.19,49.31) v1(134.19,45.63) v3(141.55,27.93) v3(141.55,27.23) v3(141.55,26.53) v3(141.55,25.83) v3(142.25,25.83) v3(142.95,25.83) v3(143.65,25.83) v3(144.35,25.83) v3(145.05,27.93) v3(145.05,27.23) v3(145.05,26.53) v3(145.05,25.83) v3(145.75,27.93) v3(145.75,27.23) v3(145.75,26.53) v3(152.78,39.88) v3(152.78,39.18) v3(152.78,38.48) v3(152.78,37.78) v3(153.48,39.88) v3(154.18,39.88) v3(154.88,39.88) v3(154.88,37.08) v3(155.58,39.88) v3(155.58,39.18) v3(155.58,38.48) v3(155.58,37.78) v3(155.58,37.08)
OUT++:
  vias: v1(138.51,24.13) v1(138.51,22.86) v1(138.51,21.59) v1(138.51,20.32) v1(139.78,21.59) v1(139.78,20.32) v1(139.78,19.05) v1(141.05,21.59) v1(141.05,20.32) v1(141.05,19.05) v1(142.32,24.13) v1(142.32,20.32) v1(142.32,19.05) v1(143.59,24.13) v1(143.59,20.32) v1(143.59,19.05) v1(144.86,24.13) v1(144.86,22.86) v1(144.86,21.59) v1(144.86,19.05)
PG_PFS: length 49.6
  TOP w0.5: 93.88,16.38 93.88,8.16
  TOP w0.508: v3(89.31,23.55) 89.69,23.55 90.2,23.04 90.2,20.93 93.88,17.25 93.88,16.38 ; 93.88,8.16 92.02,6.3 87.5,6.3 85.73,8.07 U2.8
  BOTTOM w0.305: v3(89.31,23.55) 89.31,29.95 88.6,30.66 87.55,30.66 85.6,32.61 85.6,35.92 86.09,36.41 R77.1
REFCC: length 35.9
  TOP w0.381: v2(122.58,60.35) 116.64,60.35 114.24,57.95 114.24,47.15 116.84,44.55 R64A.2
  BOTTOM w0.381: C54.1 R47.1 ; R151.1 v2(122.58,60.35) 121.17,60.35 R138.2
  BOTTOM w0.508: R47.1 114.82,43.45 115.57,42.7 R64A.2 116.83,42.71 R152.2
RTN: length 166.2
  TOP w0.508: C9B.2 60.78,36.22 61.7,36.22 66.37,31.55 89.41,31.55 v1(91.01,29.95)
  TOP w1: v9(98.7,13.63) 96.62,15.7 95.88,16.44 95.88,18.96 90.88,23.96 v1(90.88,24.41) ; v1(51.79,69.49) 54.72,72.42 v5(57.58,72.42) 57.58,78.08 v5(56.21,79.45) ; T1.5 96.96,52.1 C30.1 91.29,37.61 C21.2 93.51,33.24 97.69,29.05 T2.2
  TOP w1.5: 61.02,38.84 62.18,38.84 67.77,33.24 89.53,33.24 C21.2
  BOTTOM w0.7: Q1.2 58.23,79.15 R5.2 56.28,79.52 v5(56.21,79.45)
  BOTTOM w1: C21.2 90.42,33.24 R74.2 ; v1(54.91,58.42) 54.91,58.45 51.79,61.57 v1(51.79,69.49) ; v5(57.58,72.42) C8.2 ; 90.96,29.9 90.96,24.49 v1(90.88,24.41) ; 90.96,29.9 VR10.2 ; 90.96,29.9 v1(91.01,29.95)
  BOTTOM w1.27: VR2.2 61.21,32.88 v1(60.35,32.88)
  BOTTOM w1.5: C9.2 72.67,68.23 v1(71.73,68.23) 71.72,68.25 71.55,68.25 71.55,68.25 70.59,68.25 70.59,68.26 70.33,68.26 70.33,68.26 v1(70.23,68.26) ; v1(60.35,32.88) v1(60.35,34.54) 60.35,36.65 C9B.2
  vias: v1(54.91,56.77) v1(56.89,60.48) v9(99.85,13.58) v9(100.42,12.42) v9(100.9,13.55) v9(101.62,12.45) v9(102.07,13.55)
VBULK: length 152.1
  TOP w1: v1(60.12,26.1) 60.2,26.1 64.02,29.92 88.29,29.92 92.41,25.8 T2.3
  BOTTOM w0.305: R35.1 96.34,1.75 68.96,1.75 68.61,2.1 68.61,10.22 70.37,11.97 C11.1
  BOTTOM w0.508: R6.1 68.22,18.32 65.41,18.32 53.47,30.26 53.47,38.9 ; v1(55.38,66.51) 56.92,66.51 v1(56.94,66.53)
  BOTTOM w0.635: C2.1 97.71,36.69 R25.1
  BOTTOM w0.762: v1(90.39,65.89) 90.39,65.25 C50.1 90.75,63.65 v1(89.43,63.65)
  BOTTOM w1: C9B.1 54.45,40.68 54.45,30.85 59.15,26.15 60.08,26.15 v1(60.12,26.1)
  BOTTOM w1.27: R17.1 83.05,57.4 U3.20
  vias: v1(50.44,41.8) v1(52.1,41.84) v1(52.12,40.01) v1(52.15,38.35) v1(55.37,65) v1(56.94,64.98) v1(71.72,76.81) v1(71.72,75.29) v1(75.74,75.31) v1(75.78,76.71)
VOUT-ADC: length 4.1
  BOTTOM w0.381: R80.2 R81.1 142.69,3.95 142.67,3.92 J10.10
VRECT: length 32.4
  TOP w0.635: v3(67.07,19.25) 64.57,16.75 v3(55.02,16.75)
  BOTTOM w0.635: v3(55.02,16.75) 50.82,16.75 44.37,23.2 L3.2 ; R8.2 67.07,20.97 v3(67.07,19.25)
  vias: v3(38.94,23.06) v3(39.29,24.16) v3(39.32,22.2) v3(40.31,24.59) v3(40.28,21.82) v3(41.35,24.18) v3(41.27,22.2) v3(41.63,23.14)
N13075229: length 5.1
  BOTTOM w0.508: 33.2,70.62 35.59,68.23 R118.1
N13075257: length 10.2
  BOTTOM w0.381: R101.1 45.81,46.1 42.82,49.1
  BOTTOM w0.508: 34.18,61.62 35.59,63.03 R118.2
N13075293: length 31.9
  TOP w3.75: 17.8,15.5 17.8,21.91 ; 26.61,30.72 C5.1
  TOP w3.81: 17.8,21.91 26.61,30.72
  BOTTOM w0.381: 42.82,37.57 45.81,40.57 R101.2
N13075621: length 5.1
  BOTTOM w0.508: R119.1 23.84,68.16 26.23,70.55
N13075629: length 11.3
  BOTTOM w0.381: R102.1 25.53,45.81 28.82,49.1
  BOTTOM w0.508: R119.2 23.84,62.95 25.24,61.55 26.23,61.55
N13075705: length 6.6
  BOTTOM w0.381: 28.82,37.57 28.82,38.16 25.53,41.45 R102.2
N13076159: length 4.7
  BOTTOM w0.7: RL1.2 62.98,78.21 Q1.3
  BOTTOM w1: RL1.2 64.33,79.56 D1.2
N13076167: length 2.5
  BOTTOM w0.8: D1.1 66.12,74.7 66.12,74.69 R125.2
N13076321: length 4
  BOTTOM w0.7: R4.1 60.22,75.52 60.22,76.79 Q1.1 59.48,77.52 57.99,77.52 R5.1
N13076547: length 7.3
  BOTTOM w0.762: R8.1 66.95,25.85 68.77,27.67 R9.2
N13076615:
  vias: v1(65.15,9.64) v1(65.28,11.04)
N13076627: length 2.3
  BOTTOM w1: R7.1 69.67,25.35 R6.2
N13076649: length 18.2
  TOP w0.762: U2.7 86.7,18 85.67,19.03 84.67,19.03 v8(84.2,19.5) 83.2,19.5 80.74,21.96 v9(77.95,21.96)
  BOTTOM w0.635: C18.1 82.72,20.6 82.96,20.37 83.16,20.37 84,19.52 84.14,19.52 84.14,19.5 v8(84.2,19.5)
  BOTTOM w0.762: R14.2 76.4,23.27 R16.1 78.33,22.34 v9(77.95,21.96)
N13076657: length 8
  BOTTOM w0.762: C13.1 R12.1 80.85,19.15 81.65,18.35 84.03,18.35 84.77,17.61 U2.9
N13076673: length 2.4
  BOTTOM w0.762: R10.1 75.36,25.77 R9.1
N13076695: length 6.7
  TOP w0.762: U2.6 87.66,12.28 87.67,12.27 R13.1 88.65,11.04 89.93,9.76 C12.1
N13076727: length 17.4
  TOP w0.762: U2.5 88.63,18.46 86.5,20.59 v4(84.82,20.59) 80.8,24.61 v3(80.8,24.63)
  BOTTOM w0.508: v4(84.82,20.59) 84.61,20.8 C15.1 84.69,21.48 R15.1
  BOTTOM w0.762: R10.2 79.41,25.02 80.38,25.02 80.77,24.63 v3(80.8,24.63)
N13076745: length 2.6
  BOTTOM w0.508: R14.1 72.67,22.95 72.97,23.26 R7.2
N13076899: length 47
  TOP w0.762: U2.4 89.59,12.26 90.67,11.19 C12.2 91.83,11.19 92.3,10.71 92.3,8.37 91.57,7.65 C16.2
  BOTTOM w0.254: U2.4 89.59,14.81 89.79,15.01 90.75,15.01 91.62,15.87 91.62,16.82 89.48,18.94 89.48,20.02 89.23,20.27 87.09,20.27 86.03,21.32 C15.2
  BOTTOM w0.508: C17.2 90.89,18.61 92.18,17.31 92.18,15.65 90.49,13.96 U2.4 ; C18.2 82.72,23.73 83.74,24.74 86.51,24.74 86.87,24.38 86.87,23.37 R15.2 86.83,22.19 C15.2
  BOTTOM w0.635: C15.2 86.1,21.34 C14.2
  BOTTOM w0.762: C18.2 82.38,23.27 R16.2 80.85,22.89 R12.2 C13.2
